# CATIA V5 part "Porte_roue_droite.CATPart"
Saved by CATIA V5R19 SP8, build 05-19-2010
Part number: Porte_roue_droite
Bounding box of the stored display mesh (mm): x 840 to 960, y 0 to 1559.986, z -910 to -140
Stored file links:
  G:\EU_thinkMotion\CFAO_2010\MMS_groupe2\MMS_groupe2\OK\mmartini\mmartiniCFAO\Porte_roue_droite.CATPart
  C:\Users\Mathieu Martini\Desktop\CFAO\Animation\CFAO.CATProduct
  G:\EU_thinkMotion\CFAO_2010\MMS_groupe2\MMS_groupe2\OK\mmartini\mmartiniCFAO\Squelette.CATPart
  G:\EU_thinkMotion\CFAO_2010\MMS_groupe2\MMS_groupe2\OK\mmartini\mmartiniCFAO\jambe_roue_droite.CATPart
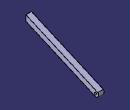
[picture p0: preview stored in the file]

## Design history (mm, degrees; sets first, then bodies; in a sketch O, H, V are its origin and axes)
External parameters (linked from other documents)
  External.diametre_canon = 150 mm
  External.diametre_verin = 120 mm
AxisSystem1: origin (0, 0, 0), X (1, 0, 0), Y (0, 1, 0), Z (0, 0, 1)
Set1
  Sketch1 on Plane1, origin (0, 0, 0), H (-1, 0, 0), V (0, 0, 1)
    line L1 (-960, -140) -> (-840, -140)
    line L2 (-840, -140) -> (-840, -260)
    line L3 (-840, -260) -> (-960, -260)
    line L4 (-960, -260) -> (-960, -140)
    reference intersected line E1 through (-825, 0) direction (0, -1) from Plane2
    reference projected line E2 through (0, -200) direction (-1, 0) from Line1
    distance L2 E1 = 15 {= (External.diametre_canon -External.diametre_verin )/2}
    distance L4 L2 = 120 {= External.diametre_verin}
    distance L3 L1 = 120 {= External.diametre_verin}
    distance E2 L3 = 60 {= External.diametre_verin /2}
    horizontal: L1 H, L3 H
    vertical: L2 V, L4 V
  Sketch2 on face of DatumSurface1, origin (840, 0, 0), H (0, 1, 0), V (0, 0, 1)
    point P1 (0, -200)
    reference intersected line E1 through (0, 0) direction (0, 1) from Plane1
    line L1 (0, -265.3911) -> (1476.1436, -905.0533)
    point P2 (0, -265.3911)
    reference intersected line E2 through (0, 0) direction (0, 1) from Plane1
    line L2 (0, -134.6089) -> (1523.8564, -794.9467)
    point P3 (0, -134.6089)
    reference intersected line E3 through (0, 0) direction (0, 1) from Plane1
    line L3 (0, -134.6089) -> (0, -265.3911)
    arc A1 centre (1500, -850) radius 60 from (1476.1436, -905.0533) to (1523.8564, -794.9467) ccw
    point P4 (1500, -850)
    reference projected point E4 (1500, -850) from Line3
    axis line L4 (1500, -850) -> (0, -200)
    point P5 (1500, -850)
    point P6 (0, -200)
    reference projected point E5 (0, -200) from Line1
    distance E1 P1 = 0
    distance L1 L4 = 60 {= External.diametre_verin /2}
    distance L2 L4 = 60 {= External.diametre_verin /2}
    coincidence: P2 E2, P3 E3, P4 E4, P6 E5, P5 P4
    tangency: A1 L2
Set2
  Plane1: linked copy from another document
  Plane2 "Plan_jambe_droite_roue": linked copy from another document
  Line1 "Droite_plan_de_construction_verin": linked copy from another document
  DatumSurface1: linked copy from another document
  Line2: linked copy from another document
  Line3 "axe_roue": linked copy from another document
  Point1: linked copy from another document
Body1 (main body)
  SolidCombine1: FirstComponentProfile Sketch2, FirstComponentDirection Sketch2, SecondComponentProfile Sketch1, SecondComponentDirection Sketch2.L1
  Sketch3 on face of SolidCombine1 from Sketch1.L4, origin (960, 0, 0), H (0, 1, 0), V (0, 0, 1)
    circle A1 centre (1500, -850) radius 25
    point P1 (1500, -850)
    reference projected point E1 (1500, -850) from Point1
    radius A1 = 25 {= External.diametre_canon /6}
    coincidence: P1 E1
  Pocket1: profile Sketch3, direction (-1, 0, 0), through (limit type 6)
